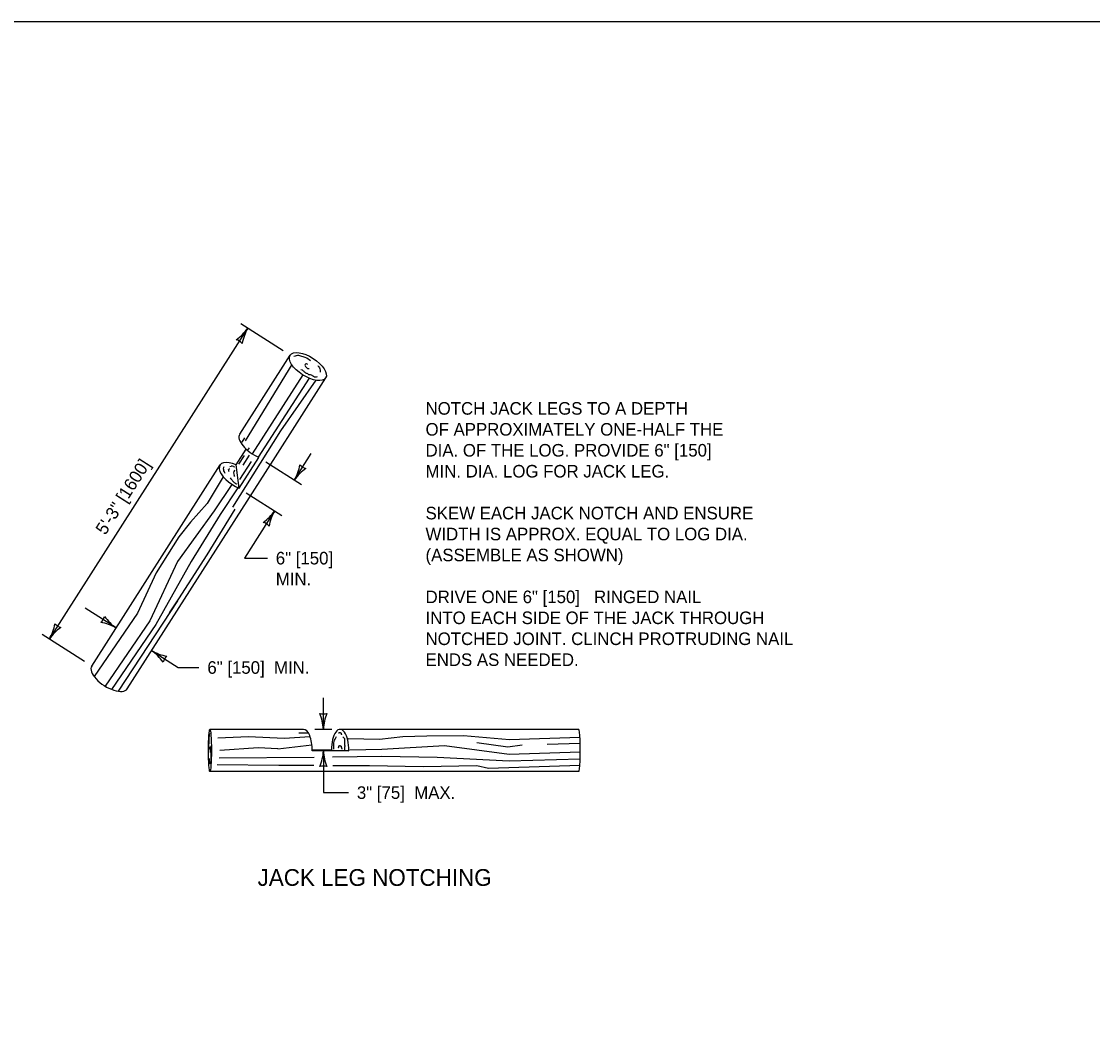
# Model space of a CAD drawing. Extents: x 49991.4 to 50021, y 49987.6 to 50011.4.
# Drawn here: x 50004.23 to 50009.35, y 49994.19 to 49999 of the extents above; entities that cross this region are included whole.
import ezdxf

# ---------------------------------------------------------------- set-up
doc = ezdxf.new("R2010")
doc.units = 0
for name, color, linetype in [('Level 1', 7, 'Continuous'), ('Level 2', 7, 'Continuous'), ('Level 3', 7, 'Continuous')]:
    doc.layers.add(name, color=color, linetype=linetype)

msp = doc.modelspace()

# ---------------------------------------------------------------- linework, layer by layer
at = {"layer": 'Level 1'}
for p, q in [((50005.2736, 49997.0277), (50005.5146, 49997.4052)), ((50005.4327, 49996.903), (50005.6841, 49997.2968)), ((50005.2846, 49996.9897), (50005.2983, 49997.0112)), ((50005.3114, 49996.9503), (50005.3196, 49996.9632)), ((50005.257, 49996.8823), (50005.3043, 49996.9565)), ((50005.2698, 49996.8851), (50005.2959, 49996.926)), ((50005.271, 49996.7701), (50005.3651, 49996.9175)), ((50005.2903, 49996.8808), (50005.3202, 49996.9275)), ((50004.5669, 49995.9208), (50005.1801, 49996.8812)), ((50004.7364, 49995.8124), (50005.4327, 49996.903)), ((50005.2204, 49996.8585), (50005.2205, 49996.8587)), ((50005.2206, 49996.8589), (50005.221, 49996.8595)), ((50005.2242, 49996.862), (50005.2249, 49996.8622)), ((50005.227, 49996.8739), (50005.2331, 49996.8751)), ((50005.2446, 49996.874), (50005.2503, 49996.8716)), ((50005.2484, 49996.8552), (50005.2501, 49996.8572)), ((50005.271, 49996.7701), (50005.257, 49996.8823)), ((50005.2738, 49996.8111), (50005.3293, 49996.898)), ((50005.2226, 49996.8504), (50005.2206, 49996.853)), ((50005.2442, 49996.8429), (50005.2442, 49996.8433)), ((50005.2508, 49996.8267), (50005.2479, 49996.8308)), ((50005.5781, 49995.6185), (50005.1314, 49995.6185)), ((50005.6025, 49995.5998), (50005.5567, 49995.5998)), ((50006.8926, 49995.6185), (50005.7531, 49995.6185)), ((50006.8992, 49995.5507), (50006.741, 49995.5461)), ((50005.7112, 49995.5193), (50005.6201, 49995.5193)), ((50005.795, 49995.5165), (50005.6201, 49995.5165)), ((50005.7112, 49995.5193), (50005.795, 49995.5165)), ((50006.8926, 49995.4174), (50005.1315, 49995.4174))]:
    msp.add_line(p, q, dxfattribs=at)
msp.add_lwpolyline([(49999.3835, 49998.9992), (50016.7501, 49998.9992), (50016.7501, 49987.7988), (49999.3835, 49987.7988)], close=True, dxfattribs=at)
for points in [[(50005.5224, 49997.3604), (50005.3, 49996.996)], [(50005.6378, 49997.2855), (50005.4689, 49997.0442), (50005.2398, 49996.6801)], [(50005.5757, 49997.3108), (50005.333, 49996.9344)], [(50005.605, 49997.2955), (50005.3623, 49996.9187)], [(50005.1954, 49996.8246), (50005.1177, 49996.6973), (50005.039, 49996.6074), (50004.9827, 49996.5378), (50004.8754, 49996.3657), (50004.786, 49996.1739), (50004.5786, 49995.8705)], [(50005.2357, 49996.7877), (50005.1521, 49996.6619), (50004.9765, 49996.4194), (50004.8452, 49996.1367), (50004.6316, 49995.8242)], [(50005.2647, 49996.7716), (50005.1801, 49996.6446), (50005.0424, 49996.42), (50004.8727, 49996.1189), (50004.661, 49995.8096)], [(50005.2501, 49996.6694), (50005.1167, 49996.4514), (50004.9385, 49996.1748), (50004.9764, 49996.2316), (50004.6929, 49995.8007)], [(50005.6104, 49995.5824), (50005.4861, 49995.5746), (50005.3158, 49995.5823), (50005.1692, 49995.5768)], [(50005.7913, 49995.5752), (50005.9416, 49995.5722), (50006.0531, 49995.5851), (50006.1667, 49995.587), (50006.3421, 49995.5884), (50006.5613, 49995.5701), (50006.898, 49995.5806)], [(50005.4556, 49995.5248), (50005.3614, 49995.5304), (50005.1781, 49995.518)], [(50005.4556, 49995.5248), (50005.6186, 49995.5443)], [(50005.7996, 49995.5213), (50005.953, 49995.5241), (50006.2518, 49995.5416), (50006.5608, 49995.5002), (50006.8995, 49995.5108)], [(50006.6216, 49995.5437), (50006.5541, 49995.5328), (50006.4056, 49995.554)], [(50005.1753, 49995.4833), (50005.6287, 49995.4851)], [(50005.7172, 49995.4868), (50005.9526, 49995.4912), (50006.216, 49995.4864), (50006.561, 49995.4674), (50006.899, 49995.4782)], [(50005.166, 49995.4503), (50005.4597, 49995.4476), (50005.6276, 49995.4468)], [(50005.7184, 49995.4463), (50005.894, 49995.4455)], [(50005.894, 49995.4455), (50006.1495, 49995.4406), (50006.4062, 49995.4454), (50006.4623, 49995.4337), (50006.8975, 49995.4468)]]:
    msp.add_lwpolyline(points, dxfattribs=at)
for centre, radius, start, end in [((50005.2247, 49996.856), 0.005, 149.082, 215.7536), ((50005.2162, 49996.8613), 0.005, 329.082, 331.3912), ((50005.2253, 49996.8571), 0.005, 103.518, 151.3912), ((50005.237, 49996.8555), 0.02, 67.5921, 101.2679), ((50005.2642, 49996.8428), 0.02, 141.8441, 178.5948), ((50005.2642, 49996.8424), 0.02, 178.5948, 215.476)]:
    msp.add_arc(centre, radius, start, end, dxfattribs=at)
for centre, major_axis, ratio in [((50005.5993, 49997.351), (-0.0847, 0.0542), 0.462929), ((50005.1314, 49995.5179), (0, 0.1006), 0.069439)]:
    msp.add_ellipse(centre, major_axis=major_axis, ratio=ratio, dxfattribs=at)
for centre, major_axis, ratio, start_param, end_param in [((50005.3583, 49996.9735), (-0.0847, 0.0542), 0.462929, 0, 1.935586), ((50005.2642, 49996.8261), (-0.0847, 0.0542), 0.462929, 5.082678, 8.21875), ((50004.6517, 49995.8666), (-0.0847, 0.0542), 0.462929, 6.283184, 9.425644), ((50005.5782, 49995.5179), (-0.0001, 0.1006), 0.416637, 4.698139, 6.283283), ((50005.7531, 49995.5179), (-0.0001, 0.1006), 0.416637, 4.698139, 7.839732), ((50006.8926, 49995.5179), (0, 0.1006), 0.069439, 3.141147, 6.283606)]:
    msp.add_ellipse(centre, major_axis=major_axis, ratio=ratio, start_param=start_param, end_param=end_param, dxfattribs=at)
for points in [[(50005.6122, 49997.3791), (50005.5868, 49997.3936), (50005.5647, 49997.4006), (50005.5554, 49997.4031), (50005.5324, 49997.3994)], [(50005.5656, 49997.3376), (50005.5765, 49997.3314), (50005.5871, 49997.3216), (50005.5999, 49997.3153), (50005.6016, 49997.3133), (50005.6072, 49997.3129), (50005.6201, 49997.3084), (50005.6255, 49997.3044), (50005.6348, 49997.3019), (50005.6443, 49997.3029)], [(50005.5995, 49997.3603), (50005.5922, 49997.3644), (50005.5863, 49997.3612), (50005.5858, 49997.3541), (50005.5892, 49997.3502), (50005.5981, 49997.3424), (50005.6056, 49997.3418)], [(50005.6465, 49997.3567), (50005.6516, 49997.3491), (50005.6566, 49997.3398), (50005.6576, 49997.3289), (50005.6572, 49997.3236)], [(50005.2045, 49996.8396), (50005.2006, 49996.8478), (50005.1971, 49996.8578), (50005.1976, 49996.8687), (50005.1988, 49996.874)], [(50005.2276, 49996.82), (50005.2354, 49996.8105), (50005.2447, 49996.8), (50005.2569, 49996.7912), (50005.2605, 49996.7892)], [(50005.1269, 49995.5222), (50005.1271, 49995.5514), (50005.128, 49995.5739), (50005.1284, 49995.583), (50005.1307, 49995.6004)], [(50005.7231, 49995.5242), (50005.7225, 49995.5469), (50005.7289, 49995.5722), (50005.7358, 49995.5845)], [(50005.7469, 49995.6011), (50005.7471, 49995.6014), (50005.7477, 49995.6019), (50005.7484, 49995.6025), (50005.7488, 49995.6027), (50005.7492, 49995.6029), (50005.7501, 49995.6033), (50005.751, 49995.6036), (50005.7514, 49995.6036), (50005.7515, 49995.6037), (50005.7516, 49995.6037), (50005.7517, 49995.6037), (50005.7521, 49995.6037), (50005.7524, 49995.6036), (50005.7532, 49995.6033), (50005.7536, 49995.6031), (50005.754, 49995.6029), (50005.7544, 49995.6027), (50005.7548, 49995.6024), (50005.7562, 49995.6013), (50005.7568, 49995.6008), (50005.7571, 49995.6005), (50005.7574, 49995.6003), (50005.758, 49995.5997), (50005.7582, 49995.5993), (50005.7583, 49995.599), (50005.7585, 49995.5984), (50005.7586, 49995.5978), (50005.7586, 49995.5971), (50005.7586, 49995.5965), (50005.7586, 49995.5959), (50005.7586, 49995.5953), (50005.7595, 49995.5923)], [(50005.1303, 49995.5228), (50005.1303, 49995.5312), (50005.1312, 49995.5344), (50005.1321, 49995.531), (50005.1324, 49995.526), (50005.1326, 49995.5143), (50005.1321, 49995.5077)], [(50005.1359, 49995.5392), (50005.1358, 49995.5267), (50005.1361, 49995.5125), (50005.1359, 49995.4983), (50005.136, 49995.4958), (50005.1356, 49995.4908), (50005.1352, 49995.4775), (50005.1352, 49995.4708), (50005.1348, 49995.4616), (50005.1339, 49995.4542)], [(50005.1269, 49995.4813), (50005.1275, 49995.4729), (50005.1282, 49995.4637), (50005.1295, 49995.4569), (50005.1302, 49995.4544)]]:
    msp.add_spline(points, degree=3, dxfattribs=at)
for points in [[(50005.7661, 49995.5833), (50005.7734, 49995.5773), (50005.7739, 49995.5744), (50005.7737, 49995.5705), (50005.7737, 49995.5681), (50005.7736, 49995.5657), (50005.7735, 49995.5634), (50005.7734, 49995.5622), (50005.7734, 49995.561), (50005.7733, 49995.5598), (50005.7733, 49995.5586), (50005.7733, 49995.5574), (50005.7733, 49995.5562), (50005.7732, 49995.5515), (50005.7738, 49995.5468), (50005.7746, 49995.5421), (50005.7746, 49995.5418), (50005.7747, 49995.5416), (50005.7748, 49995.5414), (50005.7749, 49995.5412), (50005.775, 49995.541), (50005.7751, 49995.5408), (50005.7752, 49995.5406), (50005.7754, 49995.5404), (50005.7755, 49995.5402), (50005.7756, 49995.54), (50005.7756, 49995.5398), (50005.7756, 49995.5395), (50005.7756, 49995.5391), (50005.7756, 49995.5387), (50005.7754, 49995.5383), (50005.7753, 49995.5379), (50005.7751, 49995.5375), (50005.775, 49995.5371), (50005.7748, 49995.5366), (50005.7746, 49995.5362), (50005.7745, 49995.5358), (50005.7743, 49995.5354), (50005.7742, 49995.535), (50005.7741, 49995.5346), (50005.7739, 49995.5323), (50005.7737, 49995.5301), (50005.7737, 49995.5279), (50005.7736, 49995.5268), (50005.7736, 49995.5257), (50005.7736, 49995.5246), (50005.7737, 49995.5235), (50005.7737, 49995.5223), (50005.7738, 49995.5212), (50005.7741, 49995.5199), (50005.7745, 49995.5185), (50005.7749, 49995.5172)], [(50005.7461, 49995.5295), (50005.7461, 49995.5309), (50005.7462, 49995.5323), (50005.7462, 49995.5337), (50005.7463, 49995.5344), (50005.7463, 49995.5351), (50005.7463, 49995.5358), (50005.7463, 49995.5361), (50005.7464, 49995.5365), (50005.7464, 49995.5368), (50005.7464, 49995.537), (50005.7464, 49995.5371), (50005.7464, 49995.5373), (50005.7464, 49995.5375), (50005.7464, 49995.5377), (50005.7465, 49995.5378), (50005.7465, 49995.5382), (50005.7468, 49995.5385), (50005.7471, 49995.5388), (50005.7474, 49995.5392), (50005.7479, 49995.5395), (50005.7484, 49995.5399), (50005.7489, 49995.5402), (50005.7495, 49995.5405), (50005.7501, 49995.5407), (50005.7504, 49995.5408), (50005.7506, 49995.5409), (50005.751, 49995.541), (50005.7511, 49995.541), (50005.7512, 49995.5411), (50005.7514, 49995.5411), (50005.7514, 49995.5411), (50005.7515, 49995.5411), (50005.7515, 49995.5411), (50005.7516, 49995.5411), (50005.7516, 49995.5411), (50005.7516, 49995.5411), (50005.7516, 49995.5411), (50005.7517, 49995.5411), (50005.7517, 49995.5411), (50005.7518, 49995.5411), (50005.7519, 49995.5411), (50005.7521, 49995.5411), (50005.7522, 49995.5411), (50005.7523, 49995.541), (50005.7524, 49995.541), (50005.7527, 49995.5409), (50005.753, 49995.5408), (50005.7532, 49995.5408), (50005.7538, 49995.5405), (50005.7543, 49995.5402), (50005.7548, 49995.5399), (50005.7553, 49995.5395), (50005.7558, 49995.5391), (50005.7562, 49995.5387), (50005.7564, 49995.5386), (50005.7566, 49995.5384), (50005.7568, 49995.5382), (50005.7569, 49995.5381), (50005.757, 49995.538), (50005.7571, 49995.5379), (50005.7572, 49995.5379), (50005.7573, 49995.5378), (50005.7574, 49995.5377), (50005.7579, 49995.5373), (50005.7582, 49995.5369), (50005.7583, 49995.5365), (50005.7585, 49995.536), (50005.7586, 49995.5356), (50005.7586, 49995.5352), (50005.7586, 49995.5348), (50005.7586, 49995.5344), (50005.7586, 49995.534), (50005.7586, 49995.5337), (50005.7586, 49995.5335), (50005.7586, 49995.5333), (50005.7586, 49995.5331), (50005.7586, 49995.5329), (50005.7586, 49995.5327), (50005.7588, 49995.532), (50005.7589, 49995.5313), (50005.7592, 49995.5306), (50005.7594, 49995.5299), (50005.7597, 49995.5292), (50005.7599, 49995.5285), (50005.7601, 49995.5278), (50005.7603, 49995.5271), (50005.7605, 49995.5264), (50005.7607, 49995.5257), (50005.7609, 49995.525), (50005.7609, 49995.5243)]]:
    msp.add_open_spline(points, degree=3, dxfattribs=at)
at = {"layer": 'Level 3'}
for p, q in [((50004.3646, 49996.0499), (50005.3123, 49997.5343)), ((50005.4809, 49997.4267), (50005.2786, 49997.5558)), ((50005.5346, 49996.8093), (50005.6153, 49996.9357)), ((50005.3988, 49996.896), (50005.5683, 49996.7878)), ((50005.3047, 49996.7486), (50005.4742, 49996.6404)), ((50004.6832, 49996.1028), (50004.5358, 49996.1969)), ((50004.5332, 49995.9423), (50004.3309, 49996.0714)), ((50005.6731, 49995.6185), (50005.6731, 49995.7685)), ((50005.7131, 49995.6185), (50005.6331, 49995.6185))]:
    msp.add_line(p, q, dxfattribs=at)
for points in [[(50005.4405, 49996.6619), (50005.2963, 49996.4361), (50005.4059, 49996.4361)], [(50004.8527, 49995.9946), (50004.9792, 49995.9139), (50005.0792, 49995.9139)], [(50005.6731, 49995.5165), (50005.6731, 49995.3165), (50005.7931, 49995.3165)]]:
    msp.add_lwpolyline(points, dxfattribs=at)
for centre, radius, start, end in [((50005.13, 49997.6616), 0.2223, 304.901, 325.0845), ((50005.5146, 49997.4188), 0.233, 150.2723, 169.5221), ((50005.2433, 49997.4262), 0.0548, 39.5838, 75.3061), ((50005.3424, 49996.9211), 0.2223, 329.8054, 349.989), ((50005.7246, 49996.6744), 0.233, 125.3678, 144.6177), ((50005.6036, 49996.9174), 0.0548, 219.5838, 255.3061), ((50005.2505, 49996.7968), 0.233, 305.3678, 324.6177), ((50005.6327, 49996.5501), 0.2223, 149.8054, 169.989), ((50005.3715, 49996.5538), 0.0548, 39.5838, 75.3061), ((50004.5751, 49996.1718), 0.0548, 309.5838, 345.3061), ((50004.8181, 49996.2928), 0.233, 215.3678, 234.6177), ((50004.1623, 49996.1655), 0.233, 330.2723, 349.5221), ((50004.5469, 49995.9227), 0.2223, 124.901, 145.0845), ((50004.4336, 49996.158), 0.0548, 219.5838, 255.3061), ((50004.5713, 49995.9107), 0.2223, 59.8054, 79.989), ((50004.7255, 49995.8123), 0.2223, 34.901, 55.0845), ((50004.9683, 49996.1969), 0.233, 240.2723, 259.5221), ((50004.9608, 49995.9256), 0.0548, 129.5838, 165.3061), ((50005.6731, 49995.7467), 0.0548, 252.1388, 287.8612), ((50005.4403, 49995.607), 0.233, 2.8273, 22.0772), ((50005.8952, 49995.6093), 0.2223, 157.456, 177.6395), ((50005.4509, 49995.5257), 0.2223, 337.456, 357.6395), ((50005.9058, 49995.528), 0.233, 182.8273, 202.0772), ((50005.6731, 49995.3883), 0.0548, 72.1388, 107.8612)]:
    msp.add_arc(centre, radius, start, end, dxfattribs=at)

# ---------------------------------------------------------------- texts
at = {"layer": 'Level 2'}
for s, height, p in [('NOTCH JACK LEGS TO A DEPTH', 0.06, (50006.161, 49997.1212)), ('OF APPROXIMATELY ONE-HALF THE', 0.06, (50006.161, 49997.0212)), ('DIA. OF THE LOG. PROVIDE 6" [150]', 0.06, (50006.161, 49996.9212)), ('MIN. DIA. LOG FOR JACK LEG.', 0.06, (50006.161, 49996.8212)), ('SKEW EACH JACK NOTCH AND ENSURE', 0.06, (50006.161, 49996.6212)), ('WIDTH IS APPROX. EQUAL TO LOG DIA.', 0.06, (50006.161, 49996.5212)), ('(ASSEMBLE AS SHOWN)', 0.06, (50006.161, 49996.4212)), ('DRIVE ONE 6" [150]   RINGED NAIL', 0.06, (50006.161, 49996.2212)), ('INTO EACH SIDE OF THE JACK THROUGH', 0.06, (50006.161, 49996.1212)), ('NOTCHED JOINT. CLINCH PROTRUDING NAIL', 0.06, (50006.161, 49996.0212)), ('ENDS AS NEEDED.', 0.06, (50006.161, 49995.9212)), ('JACK LEG NOTCHING', 0.08, (50005.3591, 49994.8711))]:
    msp.add_text(s, height=height, dxfattribs=at).set_placement(p)
for s, rotation, p in [('5\'-3" [1600]', 57.445, (50004.6319, 49996.5429)), ('6" [150]', 360, (50005.4459, 49996.4061)), ('MIN.', 360, (50005.4459, 49996.3061)), ('6" [150]  MIN.', 360, (50005.1192, 49995.8839)), ('3" [75]  MAX.', 359.9993, (50005.8331, 49995.2865))]:
    msp.add_text(s, height=0.06, rotation=rotation, dxfattribs=at).set_placement(p)

doc.saveas('drawing.dxf')
